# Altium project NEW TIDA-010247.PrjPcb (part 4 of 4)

## Sheet AUX Power Supply #2 Card.SchDoc
size A3; Date: Not shown in title block; ApprovedBy: Not shown in title block; CheckedBy: Not shown in title block; Author: Not shown in title block; CompanyName: Not shown in title block; Engineer: Not shown in title block; Organization: Not shown in title block; Address1: Not shown in title block; Address2: Not shown in title block; Address3: Not shown in title block; Address4: Not shown in title block; DocumentNumber: 1; Revision: Use project parameter SCH_Rev; SheetNumber: 7; SheetTotal: 9; PageSetup: Record=PageOptions¦CenterHorizontal=True¦CenterVertical=True¦PrintScale=0.69¦XCorrection=1.00¦YCorrection=1.00¦PrintKind=0¦BorderSize=5000000¦LeftOffset=0¦BottomOffset=0¦Orientation=2¦PaperLength=1000¦PaperWidth=1000¦Scale=100¦PaperSource=15¦PrintQuality=600¦MediaType=1¦DitherType=10¦PaperKind=Letter¦PrintScaleMode=1
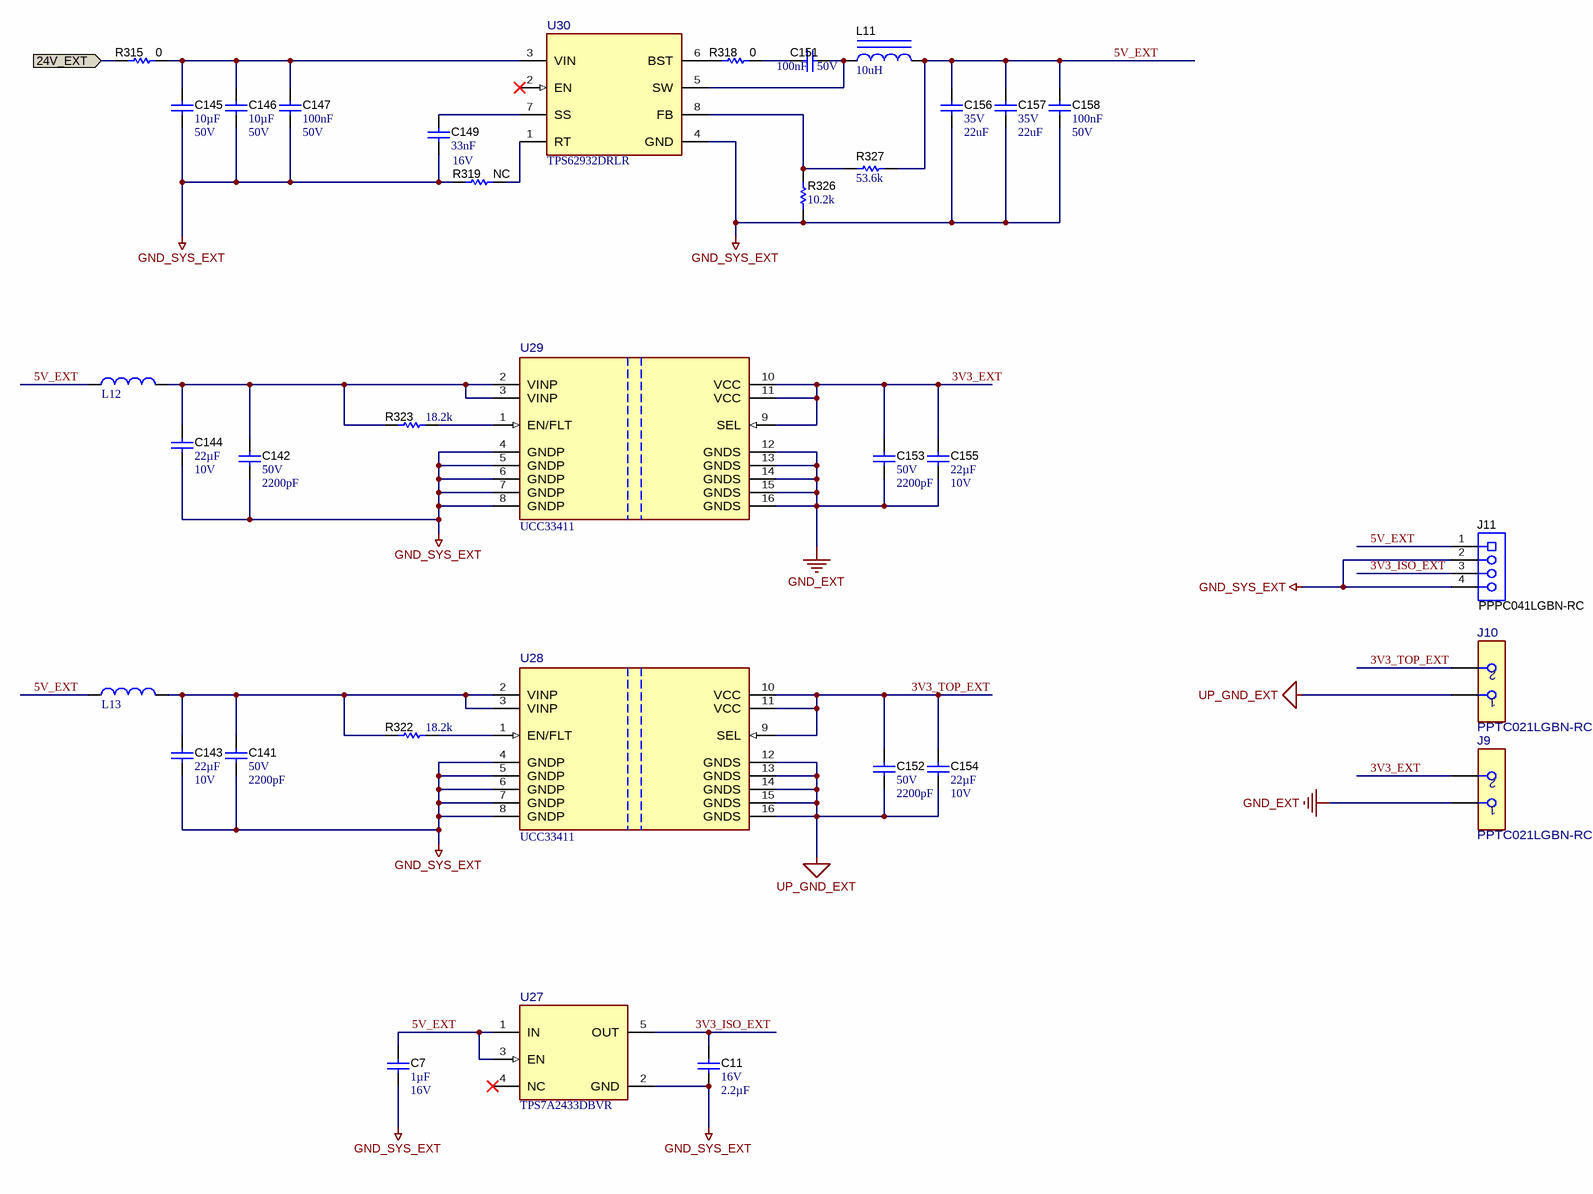
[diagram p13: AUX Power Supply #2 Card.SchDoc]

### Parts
C7  Cap_F: 1µF  VDC_V: 16V  [0603]  (hidden comment: GCM188R71C105KA64D)
C11  VDC_V: 16V  Cap_F: 2.2µF  [0603]  (hidden comment: GRM188Z71C225KE43)
C141  VDC_V: 50V  ValueDisplayed: 2200pF  [0402]  (hidden comment: GCM155R71H222KA37D)
C142  VDC_V: 50V  ValueDisplayed: 2200pF  [0402]  (hidden comment: GCM155R71H222KA37D)
C143  Cap_F: 22µF  VDC_V: 10V  [0805_HV]  (hidden comment: GRM21BZ71A226ME15L)
C144  Cap_F: 22µF  VDC_V: 10V  [0805_HV]  (hidden comment: GRM21BZ71A226ME15L)
C145  ValueDisplayed: 10µF  VDC_V: 50V  [1206_190]  (hidden comment: CGA5L1X7R1H106K160AC)
C146  ValueDisplayed: 10µF  VDC_V: 50V  [1206_190]  (hidden comment: CGA5L1X7R1H106K160AC)
C147  Cap_F: 100nF  VDC_V: 50V  [0603]  (hidden comment: C0603C104K5RACAUTO)
C149  Cap_F: 33nF  VDC_V: 16V  [0603]  (hidden comment: GRM188R71C333KA01D)
C151  Cap_F: 100nF  VDC_V: 50V  [0603]  (hidden comment: C0603C104K5RACAUTO)
C152  VDC_V: 50V  ValueDisplayed: 2200pF  [0402]  (hidden comment: GCM155R71H222KA37D)
C153  VDC_V: 50V  ValueDisplayed: 2200pF  [0402]  (hidden comment: GCM155R71H222KA37D)
C154  Cap_F: 22µF  VDC_V: 10V  [0805_HV]  (hidden comment: GRM21BZ71A226ME15L)
C155  Cap_F: 22µF  VDC_V: 10V  [0805_HV]  (hidden comment: GRM21BZ71A226ME15L)
C156  VDC_V: 35V  ValueDisplayed: 22uF  [1206_180]  (hidden comment: C3216X5R1V226M160AC)
C157  VDC_V: 35V  ValueDisplayed: 22uF  [1206_180]  (hidden comment: C3216X5R1V226M160AC)
C158  Cap_F: 100nF  VDC_V: 50V  [0603]  (hidden comment: C0603C104K5RACAUTO)
J9  PPTC021LGBN-RC  [FP-PPTC021LGBN-RC_CONN_HDR2-MFG]
J10  PPTC021LGBN-RC  [FP-PPTC021LGBN-RC_CONN_HDR2-MFG]
J11  PPPC041LGBN-RC  [SULLINS_PPPC041LGBN-RC]
L11  ValueDisplayed: 10uH  [WE-XHMI_6060]  (hidden comment: 74439346100)
L12  74479275222  [WE-PMCI_0805_L2W1.25H1]  (value not drawn)
L13  74479275222  [WE-PMCI_0805_L2W1.25H1]  (value not drawn)
R315  ValueDisplayed: 0  [0603]  (hidden comment: CRCW04020000Z0ED)
R318  ValueDisplayed: 0  [0603]  (hidden comment: CRCW04020000Z0ED)
R319  ValueDisplayed: NC  [0603]  (hidden comment: CRCW04020000Z0ED)  (no BOM)
R322  ValueDisplayed: 18.2k  [0603]  (hidden comment: CRCW060318K2FKEA)
R323  ValueDisplayed: 18.2k  [0603]  (hidden comment: CRCW060318K2FKEA)
R326  ValueDisplayed: 10.2k  [0603]  (hidden comment: RC0603FR-0710K2L)
R327  ValueDisplayed: 53.6k  [0603]  (hidden comment: RC0603FR-0753K6L)
U27  TPS7A2433DBVR  [DBV0005A-MFG]
U28  PartNumber: UCC33411  [DWX0016A-MFG]  (hidden comment: UCC33421-Q1)
U29  PartNumber: UCC33411  [DWX0016A-MFG]  (hidden comment: UCC33421-Q1)
U30  TPS62932DRLR  [DRL0008A-MFG]

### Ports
24V_EXT (in)

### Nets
GND_EXT: C153.2 C155.2 J9.1 U29.12(GNDS) U29.13(GNDS) U29.14(GNDS) U29.15(GNDS) U29.16(GNDS)
GND_SYS_EXT: C7.2 C11.2 C141.2 C142.2 C143.2 C144.2 C145.2 C146.2 C147.2 C149.2 C156.2 C157.2 C158.2 J11.2 J11.4 R319.1 R326.1 U27.2(GND) U28.4(GNDP) U28.5(GNDP) U28.6(GNDP) U28.7(GNDP) U28.8(GNDP) U29.4(GNDP) U29.5(GNDP) U29.6(GNDP) U29.7(GNDP) U29.8(GNDP) U30.4(GND)
UP_GND_EXT: C152.2 C154.2 J10.1 U28.12(GNDS) U28.13(GNDS) U28.14(GNDS) U28.15(GNDS) U28.16(GNDS)
3V3_EXT: C153.1 C155.1 J9.2 U29.9(SEL) U29.10(VCC) U29.11(VCC)
3V3_ISO_EXT: C11.1 J11.3 U27.5(OUT)
3V3_TOP_EXT: C152.1 C154.1 J10.2 U28.9(SEL) U28.10(VCC) U28.11(VCC)
5V_EXT: C7.1 C156.1 C157.1 C158.1 J11.1 L11.2 L12.1 L13.1 R327.1 U27.1(IN) U27.3(EN)
24V_EXT: R315.1 ; port 24V_EXT
NetC141_1: C141.1 C143.1 L13.2 R322.1 U28.2(VINP) U28.3(VINP)
NetC142_1: C142.1 C144.1 L12.2 R323.1 U29.2(VINP) U29.3(VINP)
NetC145_1: C145.1 C146.1 C147.1 R315.2 U30.3(VIN)
NetC149_1: C149.1 U30.7(SS)
NetC151_1: C151.1 R318.2
NetC151_2: C151.2 L11.1 U30.5(SW)
NetR318_1: R318.1 U30.6(BST)
NetR319_2: R319.2 U30.1(RT)
NetR322_2: R322.2 U28.1(EN/FLT)
NetR323_2: R323.2 U29.1(EN/FLT)
NetR326_2: R326.2 R327.2 U30.8(FB)

Not connected (* = marked no-connect by the designer): U27 4(NC)*; U30 2(EN)*

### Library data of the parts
C7 = CMP-0007136-1: CAP, CERM, 1 uF, 16 V, +/- 10%, X7R, AEC-Q200 Grade 1, 0603; Manufacturer: MuRata; TaMin_C: -55°C; Polarized: N; SizeAreaWB_mm2: 4.68; Value1: Unknown; U/M: EA; Value: 1uF; TaMax_C: 125°C; SizeZ_mm: 1; SizeX_mm: 1.6; SizeY_mm: 0.8; SizeArea_mm2: 1.28; AEC Qualified: Y; AEC Category: Q200
C11 = CMP-0007499-1: CAP, CERM, 2.2 uF, 16 V, +/- 10%, X7R, 0603; Manufacturer: MuRata; TaMin_C: -55°C; Polarized: N; SizeAreaWB_mm2: 4.68; Value1: Unknown; U/M: EA; Value: 2.2uF; TaMax_C: 125°C; SizeZ_mm: 1; SizeX_mm: 1.6; SizeY_mm: 0.8; SizeArea_mm2: 1.28; AEC Category: Q200
C141 C142 C152 C153 = CMP-0006357-1: CAP, CERM, 2200 pF, 50 V, +/- 10%, X7R, AEC-Q200 Grade 1, 0402; Manufacturer: MuRata; TaMin_C: -55°C; Polarized: N; SizeAreaWB_mm2: 3; Value1: Unknown; U/M: EA; Value: 2200pF; TaMax_C: 125°C; SizeZ_mm: 0.6; SizeX_mm: 1; SizeY_mm: 0.5; AEC Qualified: Y; Cap_F: 2.2nF; AEC Category: Q200
C143 C144 C154 C155 = CMP-0008377-2: CAP, CERM, 22 uF, 10 V, +/- 20%, X7R, 0805; Manufacturer: MuRata; SizeY_mm: 1.25; Cap_Case: 0805; SizeArea_mm2: 2.5; AEC Qualified: N; AEC Category: Q200; ValueDisplayed: 22uF; TaMin_C: -55°C; SizeAreaWB_mm2: 6.75; Value1: Unknown; U/M: EA; Value: 22uF; TaMax_C: 125°C; SizeZ_mm: 1.45; SizeX_mm: 2
C145 C146 = CMP-0085950-1: CAP, CERM, 10 µF, 50 V,+/- 10%, X7R, AEC-Q200 Grade 1, 1206; Manufacturer: TDK; SizeZ_mm: 1.9; Value: 10uF; Cap_Case: 1206; AEC Grade: 1; TaMin_C: -55°C; U/M: EA; SizeArea_mm2: 5.12; TaMax_C: 125°C; AEC Qualified: Y; AEC Category: Q200; SizeX_mm: 3.2; SizeY_mm: 1.6; Polarized: N; SizeAreaWB_mm2: 10.92
C147 C151 C158 = CMP-0079602-1: CAP, CERM, 0.1 µF, 50 V,+/- 10%, X7R, AEC-Q200 Grade 1, 0603; Manufacturer: Kemet; TaMin_C: -55°C; Polarized: N; SizeAreaWB_mm2: 4.68; U/M: EA; Value: 0.1uF; TaMax_C: 125°C; SizeZ_mm: 1; SizeX_mm: 1.6; SizeY_mm: 0.8; SizeArea_mm2: 1.28; AEC Qualified: Y; AEC Category: Q200; ValueDisplayed: 0.1µF
C149 = CMP-0007392-4: CAP, CERM, 0.033 uF, 16 V, +/- 10%, X7R, 0603; Manufacturer: MuRata; TaMin_C: -55°C; Polarized: N; SizeAreaWB_mm2: 4.68; Value1: Unknown; U/M: EA; TaMax_C: 125°C; SizeZ_mm: 1; SizeX_mm: 1.6; SizeY_mm: 0.8; SizeArea_mm2: 1.28; AEC Category: Q200
C156 C157 = CMP-0008667-2: CAP, CERM, 22 uF, 35 V, +/- 20%, X5R, 1206; Manufacturer: TDK; TaMin_C: -55°C; ESR_ohm: 2.398m; Polarized: N; SizeAreaWB_mm2: 10.92; Value1: 0.002398 ohm; U/M: EA; Value: 22uF; TaMax_C: 85°C; SizeZ_mm: 1.8; SizeX_mm: 3.2; SizeY_mm: 1.6; SizeArea_mm2: 5.12; Cap_F: 22µF; IRMS_A: 4.6851A; AEC Category: Q200
J9 J10 = CMP-0122186-1: 2 Position Header Connector 0.100" (2.54mm) Through Hole, Right Angle Tin; Manufacturer: Sullins; ContactFinish: Tin,Nickel; Current_A: 3A; Row_Count: 1; Voltage_V: 250V; AEC Qualified: No; Conn Gender: Female; Is Female: yes; SizeZ_mm: 2.74mm
J11 = CMP-0054639-1: Receptacle, 100mil, 4x1, Gold, R/A, TH; Manufacturer: Sullins Connector Solutions; CT: TRUE; CompType: Socket Strip; CNHeader: FALSE
L11 = CMP-0064174-2: Inductor, Shielded, Hyperflux, 10 µH, 5 A, 0.02915 ohm, SMD; Manufacturer: Wurth Elektronik; AEC Category: Q200; SizeArea_mm2: 42.8925; SizeAreaWB_mm2: 73.0925; Value2: 5A; SizeY_mm: 6.45; SizeX_mm: 6.65; AEC Qualified: N; Value: 10uH; Isat: 7.6A @ 30% inductance drop; Ind_H: 10µH; Irms: 5A @ 40C rise; DCR_ohm: 29.15m; SizeZ_mm: 6.1
L12 L13 = CMP-0100941-1: WE-PMCI SMT Power Molded Chip Inductor, size 0805, 2.2uH, 2.1A, 190mOhm; Manufacturer: Wurth Elektronik; Case/Size Code: 0805; DC Resistance: 180mOhm; Saturation Current: 2.4A; Self Resonant Frequency: 45MHz; Type: Standard
R315 R318 R319 = CRCW04020000Z0ED: RES, 0, 5%, 0.063 W, 0402; Manufacturer: Vishay-Dale; CompType: Resistor; Value: 0; Value_Code: 0000; Tolerance_%: 5; Power_W: 0.063; Value2: 0.063W; VDC_V: 50; TempCo: 200 ppm/C; SizeArea_mm2: 0.5; SizeX_mm: 1; SizeZ_mm: 0.6; EIA_Code: E24; U/M: EA; AEC Category: Q200; Green_Lifecycle: Active; Green_REACh: Passed
R322 R323 = CMP-0022097-1: RES, 18.2 k, 1%, 0.1 W, 0603; Manufacturer: Vishay-Dale; Power_W: 100mW; TempCo: 100 ppm/C; Value_Code: 18k2; U/M: EA; Value: 18.2k; EIA_Code: E96; SizeX_mm: 1.6; SizeY_mm: 0.8; SizeZ_mm: 1; Value2: 0.1W; SizeArea_mm2: 1.28; VDC_V: 75V; AEC Category: Q200
R326 = CMP-0022743-5: RES, 10.2 k, 1%, 0.1 W, 0603; Manufacturer: Yageo; Power_W: 100mW; TempCo: 100 ppm/C; Value_Code: 10k2; Value: 10.2k; EIA_Code: E96; SizeX_mm: 1.6; SizeY_mm: 0.8; SizeZ_mm: 1; Value2: 0.1W; SizeArea_mm2: 1.28; AEC Qualified: N; VDC_V: 75V; AEC Category: Q200; SizeAreaWB_mm2: 4.68
R327 = CMP-0023176-5: RES, 53.6 k, 1%, 0.1 W, 0603; Manufacturer: Yageo; Power_W: 100mW; TempCo: 100 ppm/C; Value_Code: 53k6; Value: 53.6k; EIA_Code: E96; SizeX_mm: 1.6; SizeY_mm: 0.8; SizeZ_mm: 1; Value2: 0.1W; SizeArea_mm2: 1.28; AEC Qualified: N; VDC_V: 75V; AEC Category: Q200; SizeAreaWB_mm2: 4.68
U27 = CMP-0120272-1: 200-mA, 18-V, ultra-low-IQ, low-dropout (LDO) voltage regulator with enable 5-SOT-23 -40 to 125; Manufacturer: Texas Instruments; SizeZ_mm: 1.45mm; AEC Qualified: No; Accuracy Percentage: 1.25%; Dropout Voltage: 160mV; Max Supply Voltage: 18V; Min Supply Voltage: 3.8V; Nominal Supply Current: 2-15uA; Number Of Outputs: 1; Output Type: Fixed; Output Voltage: 3.3V; Standoff Height: 0mm; TJmax_C: +125°C
U28 U29 = CMP-0120108-2: 1.5W, High-Density, >5 kVRMS Isolated DC-DC Converter; Manufacturer: Texas Instruments; SizeZ_mm: 2.6mm; AEC Qualified: No; Max Supply Voltage: 5.5V; Min Supply Voltage: 4.5V; Number Of Outputs: 1; Output Type: AdjustableProgrammable; Output Voltage: 5/5.5V; Standoff Height: 0.14mm; AEC Category: Q200; CompType: IC
U30 = CMP-0094457-2: 3.8-V to 30-V, 2-A Synchronous Buck Converter in SOT583 Package; Manufacturer: Texas Instruments; SizeZ_mm: 0.6mm; Max Duty Cycle: 98%; Min Supply Voltage: 3.8V; Output Type: AdjustableProgrammable; Number Of Outputs: 1; AEC Qualified: No; AEC Category: Q200; Nominal Supply Current: 12uA; CompType: IC; Standoff Height: 0mm; TJmax_C: +150°C; Switching Frequency: 310-2100kHz; Max Supply Voltage: 30V; Output Voltage: 0.8-22V

## Sheet Cell simulator.SchDoc
size A4; Date: Not shown in title block; ApprovedBy: Not shown in title block; CheckedBy: Not shown in title block; Author: Not shown in title block; CompanyName: Not shown in title block; Engineer: Not shown in title block; Organization: Not shown in title block; Address1: Not shown in title block; Address2: Not shown in title block; Address3: Not shown in title block; Address4: Not shown in title block; DocumentNumber: 2; Revision: Use project parameter SCH_Rev; SheetNumber: 9; SheetTotal: 10; PageSetup: Record=PageOptions¦CenterHorizontal=True¦CenterVertical=True¦PrintScale=1.00¦XCorrection=1.00¦YCorrection=1.00¦PrintKind=0¦BorderSize=5000000¦LeftOffset=0¦BottomOffset=0¦Orientation=2¦PaperLength=1000¦PaperWidth=1000¦Scale=100¦PaperSource=15¦PrintQuality=600¦MediaType=1¦DitherType=10¦PaperKind=Letter¦PrintScaleMode=1
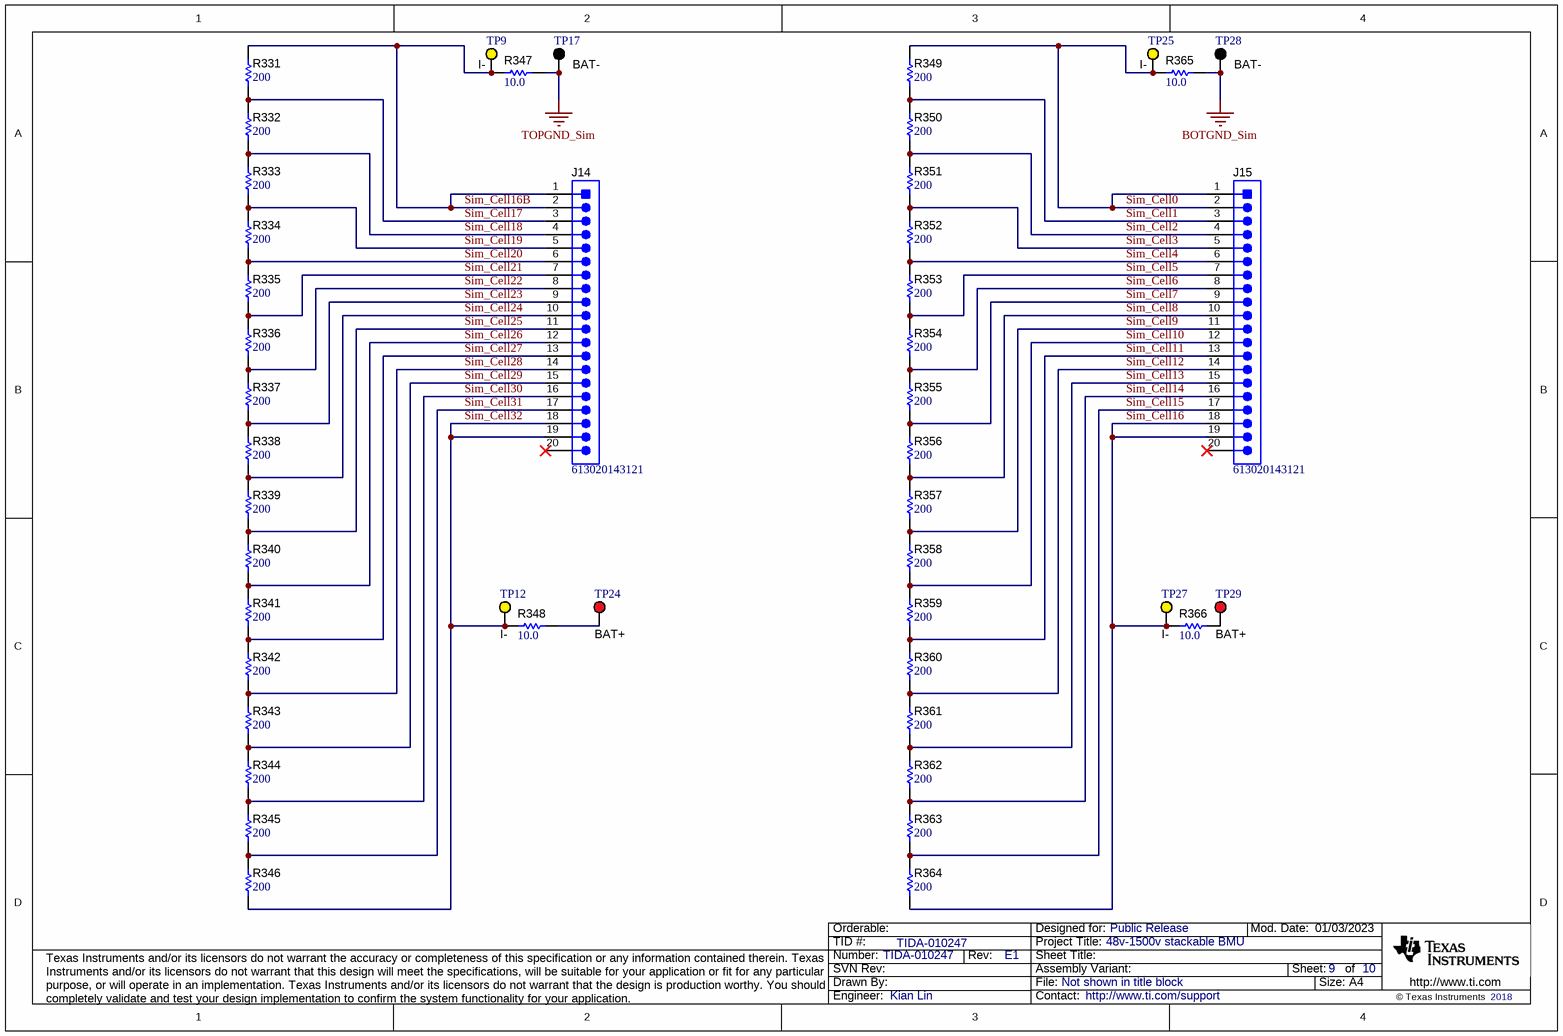
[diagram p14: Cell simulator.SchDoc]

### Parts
J14  613020143121  [TSW-120-07-G-S]
J15  613020143121  [TSW-120-07-G-S]
R331  ValueDisplayed: 200  [2512]  (hidden comment: CRCW2512200RFKEG)
R332  ValueDisplayed: 200  [2512]  (hidden comment: CRCW2512200RFKEG)
R333  ValueDisplayed: 200  [2512]  (hidden comment: CRCW2512200RFKEG)
R334  ValueDisplayed: 200  [2512]  (hidden comment: CRCW2512200RFKEG)
R335  ValueDisplayed: 200  [2512]  (hidden comment: CRCW2512200RFKEG)
R336  ValueDisplayed: 200  [2512]  (hidden comment: CRCW2512200RFKEG)
R337  ValueDisplayed: 200  [2512]  (hidden comment: CRCW2512200RFKEG)
R338  ValueDisplayed: 200  [2512]  (hidden comment: CRCW2512200RFKEG)
R339  ValueDisplayed: 200  [2512]  (hidden comment: CRCW2512200RFKEG)
R340  ValueDisplayed: 200  [2512]  (hidden comment: CRCW2512200RFKEG)
R341  ValueDisplayed: 200  [2512]  (hidden comment: CRCW2512200RFKEG)
R342  ValueDisplayed: 200  [2512]  (hidden comment: CRCW2512200RFKEG)
R343  ValueDisplayed: 200  [2512]  (hidden comment: CRCW2512200RFKEG)
R344  ValueDisplayed: 200  [2512]  (hidden comment: CRCW2512200RFKEG)
R345  ValueDisplayed: 200  [2512]  (hidden comment: CRCW2512200RFKEG)
R346  ValueDisplayed: 200  [2512]  (hidden comment: CRCW2512200RFKEG)
R347  ValueDisplayed: 10.0  [0805_HV]  (hidden comment: CRCW080510R0FKEA)
R348  ValueDisplayed: 10.0  [0805_HV]  (hidden comment: CRCW080510R0FKEA)
R349  ValueDisplayed: 200  [2512]  (hidden comment: CRCW2512200RFKEG)
R350  ValueDisplayed: 200  [2512]  (hidden comment: CRCW2512200RFKEG)
R351  ValueDisplayed: 200  [2512]  (hidden comment: CRCW2512200RFKEG)
R352  ValueDisplayed: 200  [2512]  (hidden comment: CRCW2512200RFKEG)
R353  ValueDisplayed: 200  [2512]  (hidden comment: CRCW2512200RFKEG)
R354  ValueDisplayed: 200  [2512]  (hidden comment: CRCW2512200RFKEG)
R355  ValueDisplayed: 200  [2512]  (hidden comment: CRCW2512200RFKEG)
R356  ValueDisplayed: 200  [2512]  (hidden comment: CRCW2512200RFKEG)
R357  ValueDisplayed: 200  [2512]  (hidden comment: CRCW2512200RFKEG)
R358  ValueDisplayed: 200  [2512]  (hidden comment: CRCW2512200RFKEG)
R359  ValueDisplayed: 200  [2512]  (hidden comment: CRCW2512200RFKEG)
R360  ValueDisplayed: 200  [2512]  (hidden comment: CRCW2512200RFKEG)
R361  ValueDisplayed: 200  [2512]  (hidden comment: CRCW2512200RFKEG)
R362  ValueDisplayed: 200  [2512]  (hidden comment: CRCW2512200RFKEG)
R363  ValueDisplayed: 200  [2512]  (hidden comment: CRCW2512200RFKEG)
R364  ValueDisplayed: 200  [2512]  (hidden comment: CRCW2512200RFKEG)
R365  ValueDisplayed: 10.0  [0805_HV]  (hidden comment: CRCW080510R0FKEA)
R366  ValueDisplayed: 10.0  [0805_HV]  (hidden comment: CRCW080510R0FKEA)
TP9  I-  [Keystone5009]
TP12  I-  [Keystone5009]
TP17  BAT-  [Keystone5011]
TP24  BAT+  [Keystone5010]
TP25  I-  [Keystone5009]
TP27  I-  [Keystone5009]
TP28  BAT-  [Keystone5011]
TP29  BAT+  [Keystone5010]

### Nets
BOTGND_Sim: R365.2 TP28.1
TOPGND_Sim: R347.2 TP17.1
Sim_Cell0: J15.1 J15.2 R349.2 R365.1 TP25.1
Sim_Cell1: J15.3 R349.1 R350.2
Sim_Cell2: J15.4 R350.1 R351.2
Sim_Cell3: J15.5 R351.1 R352.2
Sim_Cell4: J15.6 R352.1 R353.2
Sim_Cell5: J15.7 R353.1 R354.2
Sim_Cell6: J15.8 R354.1 R355.2
Sim_Cell7: J15.9 R355.1 R356.2
Sim_Cell8: J15.10 R356.1 R357.2
Sim_Cell9: J15.11 R357.1 R358.2
Sim_Cell10: J15.12 R358.1 R359.2
Sim_Cell11: J15.13 R359.1 R360.2
Sim_Cell12: J15.14 R360.1 R361.2
Sim_Cell13: J15.15 R361.1 R362.2
Sim_Cell14: J15.16 R362.1 R363.2
Sim_Cell15: J15.17 R363.1 R364.2
Sim_Cell16: J15.18 J15.19 R364.1 R366.1 TP27.1
Sim_Cell16B: J14.1 J14.2 R331.2 R347.1 TP9.1
Sim_Cell17: J14.3 R331.1 R332.2
Sim_Cell18: J14.4 R332.1 R333.2
Sim_Cell19: J14.5 R333.1 R334.2
Sim_Cell20: J14.6 R334.1 R335.2
Sim_Cell21: J14.7 R335.1 R336.2
Sim_Cell22: J14.8 R336.1 R337.2
Sim_Cell23: J14.9 R337.1 R338.2
Sim_Cell24: J14.10 R338.1 R339.2
Sim_Cell25: J14.11 R339.1 R340.2
Sim_Cell26: J14.12 R340.1 R341.2
Sim_Cell27: J14.13 R341.1 R342.2
Sim_Cell28: J14.14 R342.1 R343.2
Sim_Cell29: J14.15 R343.1 R344.2
Sim_Cell30: J14.16 R344.1 R345.2
Sim_Cell31: J14.17 R345.1 R346.2
Sim_Cell32: J14.18 J14.19 R346.1 R348.1 TP12.1
NetR348_2: R348.2 TP24.1
NetR366_2: R366.2 TP29.1

Not connected (* = marked no-connect by the designer): J14 20*; J15 20*

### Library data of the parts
J14 J15 = CMP-0075434-1: Header, 100mil, 20x1, Gold, TH; Manufacturer: Wurth Elektronik; Pitch_mm: 2.54; Cert_VDE: N; Gender: Male; Cert_CSA: Y; Current_A: 6.3A; Voltage_V: 550V; CT: False; Row_Count: 1; CNHeader: True
R331-R346 R349-R364 = CMP-0015526-3: RES, 200, 1%, 1 W, AEC-Q200 Grade 0, 2512; Manufacturer: Vishay-Dale; Power_W: 1W; TempCo: 100 ppm/C; Value_Code: 200R; Value: 200; EIA_Code: E96; SizeX_mm: 6.3; SizeY_mm: 3.2; SizeZ_mm: 0.71; SizeArea_mm2: 20.16; AEC Qualified: Y; VDC_V: 500V; AEC Grade: 0; AEC Category: Q200
R347 R348 R365 R366 = CMP-0020847-1: RES, 10.0, 1%, 0.125 W, 0805; Manufacturer: Vishay-Dale; Power_W: 125mW; TempCo: 100 ppm/C; Value_Code: 10R0; U/M: EA; Value: 10.0; EIA_Code: E96; Res_ohm: 10; SizeX_mm: 2; SizeY_mm: 1.25; SizeZ_mm: 1.45; Value2: 0.125W; SizeArea_mm2: 2.5; VDC_V: 150V; AEC Category: Q200
TP9 TP12 TP25 TP27 = CMP-0055146-2: Test Point, Compact, Yellow, TH; Manufacturer: Keystone Electronics; Green_REACh: Passed; ContactFinish: Silver; CT: TRUE; CNHeader: FALSE; Green_Lifecycle: Active
TP17 TP28 = CMP-0055148-1: Test Point, Multipurpose, Black, TH; Manufacturer: Keystone; PartNumber: 5011; CNHeader: FALSE; Green_Lifecycle: Active; Green_REACh: Passed; ContactFinish: Silver; CT: TRUE
TP24 TP29 = CMP-0055147-1: Test Point, Multipurpose, Red, TH; Manufacturer: Keystone; PartNumber: 5010; CNHeader: FALSE; Green_Lifecycle: Active; Green_REACh: Passed; ContactFinish: Silver; CT: TRUE

## Sheet Cover Sheet.SchDoc
size A4; Date: Not shown in title block; ApprovedBy: Not shown in title block; CheckedBy: Not shown in title block; Author: Not shown in title block; CompanyName: Not shown in title block; Engineer: Not shown in title block; Organization: Not shown in title block; Address1: Not shown in title block; Address2: Not shown in title block; Address3: Not shown in title block; Address4: Not shown in title block; DocumentNumber: 2; Revision: Use project parameter SCH_Rev; SheetNumber: 2; SheetTotal: 10; PageSetup: Record=PageOptions¦CenterHorizontal=True¦CenterVertical=True¦PrintScale=1.00¦XCorrection=1.00¦YCorrection=1.00¦PrintKind=0¦BorderSize=5000000¦LeftOffset=0¦BottomOffset=0¦Orientation=2¦PaperLength=1000¦PaperWidth=1000¦Scale=100¦PaperSource=15¦PrintQuality=600¦MediaType=1¦DitherType=10¦PaperKind=Letter¦PrintScaleMode=1
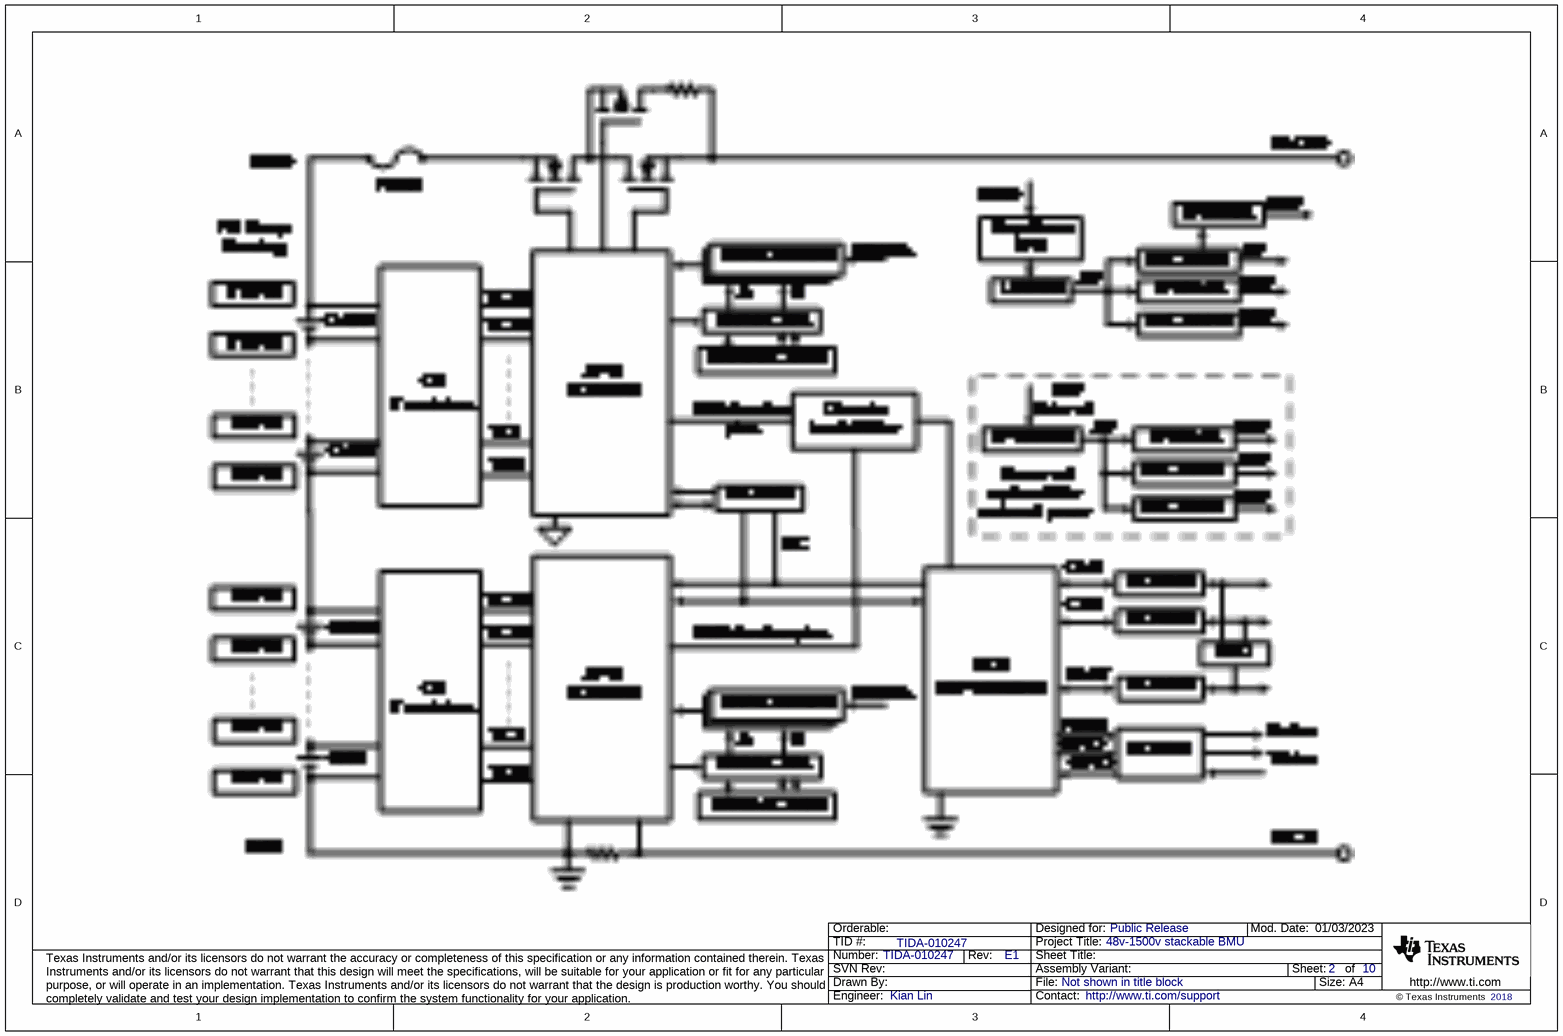
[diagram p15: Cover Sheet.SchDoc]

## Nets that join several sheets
2V5BOT: AFE and External Balancing (C81.2 D41.2 R203.2 U11.34), Temp Sensing (11 pins)
2V5TOP: AFE and External Balancing (C75.2 R50.2 U10.34), Temp Sensing (10 pins)
3V3: MCU and Interfaces (23 pins), AUX Power Supply (C136.1 R49.1 U25.5)
3V3_ISO: MCU and Interfaces (C20.2 R45.2 U8.16), AUX Power Supply (R1.1 R266.2)
3V3_TOP_ISO: MCU and Interfaces (C63.2 R41.2 R42.2 U9.8), AUX Power Supply (R48.1 R267.2)
5V_ISO: MCU and Interfaces (11 pins), AUX Power Supply (5 pins)
3V3BOT: AFE and External Balancing (C80.2 D40.2 Q20.1 U11.35), Temp Sensing (10 pins)
3V3TOP: AFE and External Balancing (8 pins), Temp Sensing (10 pins)
GND: High Level Sheet (7 pins), MCU and Interfaces (45 pins), AFE and External Balancing (37 pins), High side FETs (D19.2 D20.2), AUX Power Supply (33 pins), Temp Sensing (43 pins)
GND_SYS: High Level Sheet (J4.2 J4.4 J4.6), MCU and Interfaces (32 pins), AUX Power Supply (12 pins)
GND_SYS_EXT: High Level Sheet (J5.2), AUX Power Supply #2 Card (29 pins)
UP_GND: High Level Sheet (6 pins), MCU and Interfaces (C63.1 Q66.1 U9.5), AFE and External Balancing (36 pins), High side FETs (D16.2 D34.2 D36.2), AUX Power Supply (7 pins), Temp Sensing (43 pins)
5V: AFE and External Balancing (R224.2), AUX Power Supply (6 pins)
24V_EXT: High Level Sheet (J5.1), AUX Power Supply #2 Card (R315.1)
485A: High Level Sheet (P1.1), MCU and Interfaces (D49.1 D55.2 L9.2)
485B: High Level Sheet (P1.2), MCU and Interfaces (D49.2 D52.2 L8.2)
BAT_IN: High Level Sheet (D43.2 J1.19), AFE and External Balancing (D10.2 D2.2), AUX Power Supply (C116.1 R308.1)
BOT_ALERT: MCU and Interfaces (R11.1), AFE and External Balancing (R227.2)
BOT_BAT_IN: High Level Sheet (D45.2 J2.19), AFE and External Balancing (D6.2)
BOT_CB: MCU and Interfaces (U31.14), AFE and External Balancing (R190.1)
BOT_DDSG: High Level Sheet (D1.1), MCU and Interfaces (D17.1), High side FETs (R293.1 TP13.1)
BOT_INH: MCU and Interfaces (U31.15), Temp Sensing (R295.1)
BOT_LD: AFE and External Balancing (U11.41), High side FETs (D19.1 D35.2 R302.1)
BOT_PACK: AFE and External Balancing (U11.42), High side FETs (D20.1 R299.1)
BOT_SHUT: MCU and Interfaces (R15.1), AFE and External Balancing (C84.1 R252.2 U11.33)
BOT_WAKE: MCU and Interfaces (U31.63), AFE and External Balancing (R254.1)
BOTAFE_DDSG: High Level Sheet (D1.2), AFE and External Balancing (R222.2 R246.1)
BOTHOFF: MCU and Interfaces (R18.1), AFE and External Balancing (U11.30)
CAN0H: High Level Sheet (P3.1), MCU and Interfaces (D51.1 D53.2 L3.2)
CAN0L: High Level Sheet (P3.2), MCU and Interfaces (D51.2 D56.2 L4.2)
CAN1H: High Level Sheet (P2.1), MCU and Interfaces (D50.1 D54.2 L6.2)
CAN1L: High Level Sheet (P2.2), MCU and Interfaces (D50.2 D57.2 L7.2)
Cell0: High Level Sheet (J2.2), AFE and External Balancing (Q41.2 R185.1)
Cell1: High Level Sheet (J2.3), AFE and External Balancing (Q39.2 R149.1 R151.1 R181.1)
Cell2: High Level Sheet (J2.4), AFE and External Balancing (Q36.2 R144.1 R146.1 R177.1)
Cell3: High Level Sheet (J2.5), AFE and External Balancing (Q32.2 R140.1 R142.1 R173.1)
Cell4: High Level Sheet (J2.6), AFE and External Balancing (Q30.2 R136.1 R138.1 R169.1)
Cell5: High Level Sheet (J2.7), AFE and External Balancing (Q28.2 R132.1 R134.1 R165.1)
Cell6: High Level Sheet (J2.8), AFE and External Balancing (Q26.2 R128.1 R130.1 R161.1)
Cell7: High Level Sheet (J2.9), AFE and External Balancing (Q24.2 R124.1 R126.1 R157.1)
Cell8: High Level Sheet (J2.10), AFE and External Balancing (Q21.2 R119.1 R120.1 R122.1)
Cell9: High Level Sheet (J2.11), AFE and External Balancing (Q17.2 R83.1 R85.1 R115.1)
Cell10: High Level Sheet (J2.12), AFE and External Balancing (Q14.2 R79.1 R81.1 R111.1)
Cell11: High Level Sheet (J2.13), AFE and External Balancing (Q12.2 R75.1 R77.1 R107.1)
Cell12: High Level Sheet (J2.14), AFE and External Balancing (Q10.2 R71.1 R73.1 R103.1)
Cell13: High Level Sheet (J2.15), AFE and External Balancing (Q7.2 R68.1 R70.1 R99.1)
Cell14: High Level Sheet (J2.16), AFE and External Balancing (Q3.2 R63.1 R65.1 R95.1)
Cell15: High Level Sheet (J2.17), AFE and External Balancing (Q1.2 R59.1 R61.1 R91.1)
Cell16: High Level Sheet (D46.2 J2.18), AFE and External Balancing (R55.1 R57.1 R87.1 R152.1)
Cell16B: High Level Sheet (J1.2), AFE and External Balancing (Q43.2 R152.2 R153.1 R186.1)
Cell17: High Level Sheet (J1.3), AFE and External Balancing (Q40.2 R148.1 R150.1 R182.1)
Cell18: High Level Sheet (J1.4), AFE and External Balancing (Q37.2 R145.1 R147.1 R178.1)
Cell19: High Level Sheet (J1.5), AFE and External Balancing (Q33.2 R141.1 R143.1 R174.1)
Cell20: High Level Sheet (J1.6), AFE and External Balancing (Q31.2 R137.1 R139.1 R170.1)
Cell21: High Level Sheet (J1.7), AFE and External Balancing (Q29.2 R133.1 R135.1 R166.1)
Cell22: High Level Sheet (J1.8), AFE and External Balancing (Q27.2 R129.1 R131.1 R162.1)
Cell23: High Level Sheet (J1.9), AFE and External Balancing (Q25.2 R125.1 R127.1 R158.1)
Cell24: High Level Sheet (J1.10), AFE and External Balancing (Q22.2 R121.1 R123.1 R154.1)
Cell25: High Level Sheet (J1.11), AFE and External Balancing (Q18.2 R84.1 R86.1 R116.1)
Cell26: High Level Sheet (J1.12), AFE and External Balancing (Q15.2 R80.1 R82.1 R112.1)
Cell27: High Level Sheet (J1.13), AFE and External Balancing (Q13.2 R76.1 R78.1 R108.1)
Cell28: High Level Sheet (J1.14), AFE and External Balancing (Q11.2 R72.1 R74.1 R104.1)
Cell29: High Level Sheet (J1.15), AFE and External Balancing (Q8.2 R67.1 R69.1 R100.1)
Cell30: High Level Sheet (J1.16), AFE and External Balancing (Q4.2 R64.1 R66.1 R96.1)
Cell31: High Level Sheet (J1.17), AFE and External Balancing (Q2.2 R60.1 R62.1 R92.1)
Cell32: High Level Sheet (D44.2 J1.18), AFE and External Balancing (R56.1 R58.1 R88.1)
CSN: High Level Sheet (R3.4), AFE and External Balancing (R251.1)
CSP: High Level Sheet (R3.3), AFE and External Balancing (R239.1)
Current+: High Level Sheet (R2.2 R3.1), High side FETs (6 pins)
EN: MCU and Interfaces (R19.1), AUX Power Supply (U24.3)
NTC0: High Level Sheet (C169.1 J1.22), AFE and External Balancing (R205.2)
NTC1: High Level Sheet (C170.1 J1.21), AFE and External Balancing (R207.2)
NTC2: High Level Sheet (C171.1 J2.22), AFE and External Balancing (R225.2)
NTC3: High Level Sheet (C172.1 J2.21), AFE and External Balancing (R226.2)
PACK-: High Level Sheet (R3.2), High side FETs (5 pins)
PWM_Fan: High Level Sheet (J4.1), MCU and Interfaces (R36.2 U33.2)
SCL: MCU and Interfaces (R53.2 U9.3), AFE and External Balancing (U11.26)
SCL_TOPAFE: MCU and Interfaces (S2.4), AFE and External Balancing (U10.26)
SDA: MCU and Interfaces (R46.2 U9.2), AFE and External Balancing (U11.27)
SDA_TOPAFE: MCU and Interfaces (S2.3), AFE and External Balancing (U10.27)
TOP_ALERT: MCU and Interfaces (U31.54), AFE and External Balancing (D14.1 R231.1 R233.2)
TOP_CHG: AFE and External Balancing (U10.45), High side FETs (R259.1 TP7.1)
TOP_CP1: AFE and External Balancing (C66.1 U10.46), High side FETs (CP1.1 R262.1)
TOP_DSG: AFE and External Balancing (U10.43), High side FETs (R274.1)
TOP_LD: AFE and External Balancing (U10.41), High side FETs (7 pins)
TOP_PDSG: AFE and External Balancing (U10.39), High side FETs (D16.1 R258.1)
TOP_SHUT: MCU and Interfaces (R12.1), AFE and External Balancing (Q9.1)
TOP_TS_INH: MCU and Interfaces (R26.2), Temp Sensing (R296.1)
TOP_WAKE: MCU and Interfaces (U31.55), AFE and External Balancing (R249.1)
TS1_BOT: AFE and External Balancing (C162.2 U11.21), Temp Sensing (R298.1)
TS1_TOP: AFE and External Balancing (C21.2 U10.21), Temp Sensing (R301.1)
TSa_BOT: AFE and External Balancing (R193.1), Temp Sensing (U21.13)
TSa_TOP: AFE and External Balancing (R191.1), Temp Sensing (U14.13)
TSb_BOT: AFE and External Balancing (R217.2), Temp Sensing (U21.3)
TSb_TOP: AFE and External Balancing (R197.2), Temp Sensing (U14.3)
TSc_BOT: AFE and External Balancing (R215.2), Temp Sensing (U20.13)
TSc_TOP: AFE and External Balancing (R195.2), Temp Sensing (U13.13)
TSd_BOT: AFE and External Balancing (R212.2), Temp Sensing (U20.3)
TSd_TOP: AFE and External Balancing (R206.2), Temp Sensing (U13.3)
TSe_BOT: AFE and External Balancing (R210.2), Temp Sensing (U19.13)
TSe_TOP: AFE and External Balancing (R208.2), Temp Sensing (U12.13)
TSf_BOT: AFE and External Balancing (R202.2), Temp Sensing (U19.3)
TSf_TOP: AFE and External Balancing (R204.2), Temp Sensing (U12.3)
UCC_EN1: MCU and Interfaces (U31.19), AUX Power Supply (R310.1)
UCC_EN2: MCU and Interfaces (U31.2), AUX Power Supply (R311.1)
Wake_IN: High Level Sheet (J4.5), MCU and Interfaces (R39.1 U34.2)
Wake_OUT: High Level Sheet (J4.3), MCU and Interfaces (R38.2 U32.2)

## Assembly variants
001: not fitted C21 C24 C131 C137 C162 D41 FID1 FID2 FID3 R1 R48 R49 R52 R187 R194 R196 R205 R207 R222 R223 R225 R226 R227 R275 R317 R319 R?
